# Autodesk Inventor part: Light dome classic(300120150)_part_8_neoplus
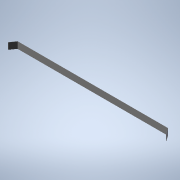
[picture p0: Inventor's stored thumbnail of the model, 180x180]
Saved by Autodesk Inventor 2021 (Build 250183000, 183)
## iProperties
Created: 2026-04
Part Number: Light dome classic(300120150)_part_8_neoplus
Material: Generic
Catalog Web Link: www.3dfindit.com
Description: Light dome classic_part_8_neoplus-
Vendor: KINGSPAN
Document SubType Name: Modeling
Designer: psAdmin
Manufacturer: KINGSPAN
Mass: 61.4652 g
Surface Area: 851.733 cm^2
Volume: 61.4652 cm^3
Density: 1 g/cm^3
Appearance: PSOLRGB-255-255-255
Category: PARTsolutions
Company: KINGSPAN
Title: Light dome classic(300120150)_part_8_neoplus
Author: Cadenas PARTsolutions
PSOL_IDENT_0: {$CADENAS_DATA/23d-libs/kingspan_kla/light_dome_classic_neoplus/parts/part_8.prj},268 {VTYP=3D},{NB=
PSOL_IDENT_1: Light dome classic(300120150)_part_8_neoplus},{LINA=Light dome classic(300120150)_part_8_neoplus},{N
PSOL_IDENT_2: N=Light dome classic_part_8_neoplus},{DATE=15.07.2024 10:56:16},{GEOMDATE=27.09.2022 13:43:52},{VERS
PSOL_IDENT_3: ION=},{LINEID=10},{WBVAR=LODLEVEL,L,W},{WBNUMERIC=W}  {NB=Light dome classic(300120150)_part_8_neopl
PSOL_IDENT_4: us},{LINA=Light dome classic(300120150)_part_8_neoplus},{KT=DUMMY},{IDNR=},{PN=Light dome classic},{
PSOL_IDENT_5: LODLEVEL=300},{L=120},{W=150},{WX=120,150,180,240,270,300},{LX=1200},{XWX=1500}
NB: Light dome classic(300120150)_part_8_neoplus
NN: Light dome classic_part_8_neoplus
NBSYN: $PN.($LODLEVEL.$L.$W.)_part_8_neoplus
LINA: Light dome classic(300120150)_part_8_neoplus
CATALOG: Light + Air
PN: Light dome classic
LODLEVEL: 300
L: 120
W: 150
SUPPLIER: KINGSPAN
ARTICLENO: Light dome classic(300120150)_part_8_neoplus
BOMINFO: Light dome classic(300120150)_part_8_neoplus
CREATOR: CADENAS GmbH
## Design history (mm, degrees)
sketch "Sketch_1"
  geometry: L1 (494.907, 293)-(493.076, 293); L2 (493.076, 293)-(469.096, 258.753); L3 (469.096, 258.753)-(-469.096, 258.753); L4 (-469.096, 258.753)-(-493.076, 293); L5 (-493.076, 293)-(-494.907, 293); L6 (-494.907, 293)-(-469.877, 257.253); L7 (-469.877, 257.253)-(469.877, 257.253); L8 (469.877, 257.253)-(494.907, 293)
  constraints: 16 end point
extrude "Extrusion1" join sketch "Sketch_1" stored distance "d0" = 40; taper "d1" = 0 deg
node "IP_8_XY"
node "IP_8_YZ"
node "IP_8_ZX"
node "IP_8_X"
node "IP_8_Y"
node "IP_8_Z"
node "IP_8_Center"
body "Solid1"
other parameters: "d2" = 0
